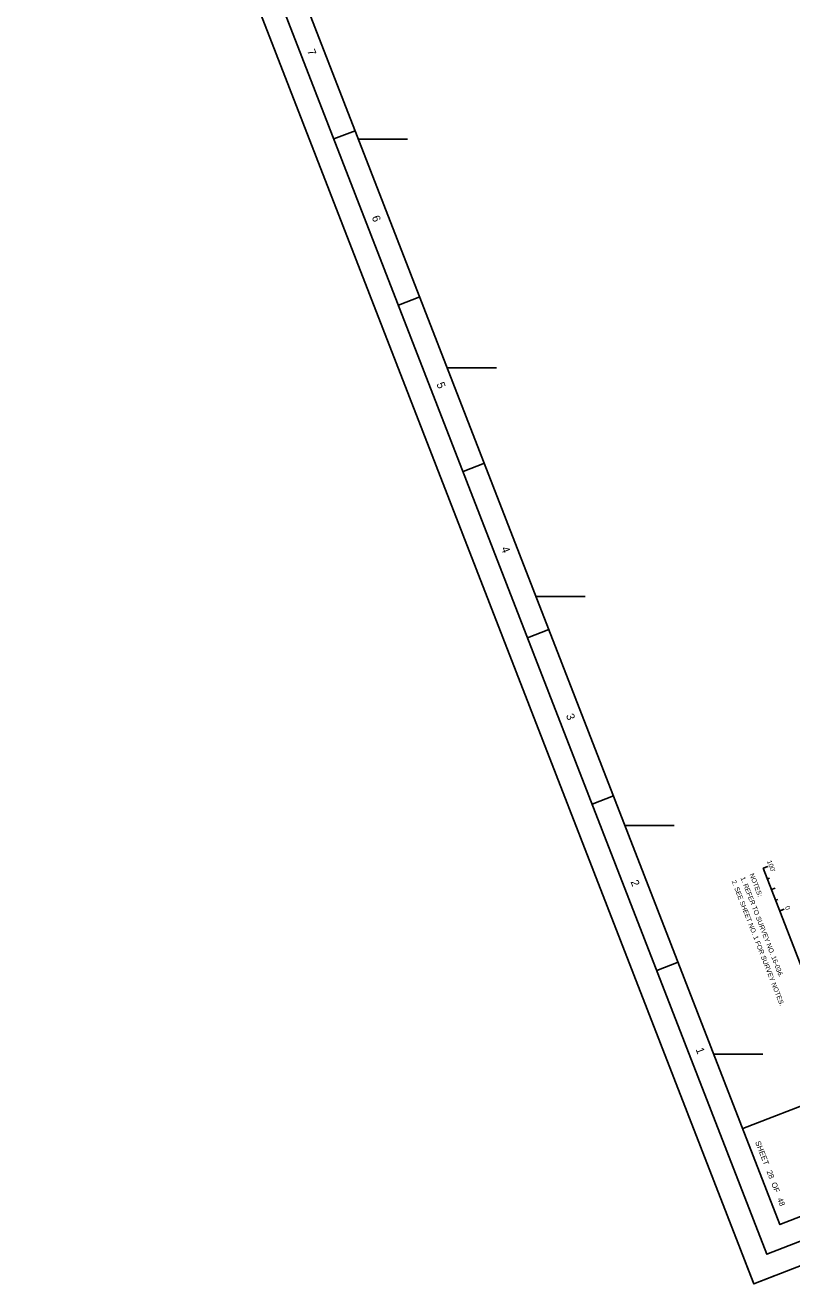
# Model space of a CAD drawing. Extents: x 588973 to 593734, y 821498 to 826830.
# Drawn here: x 588973 to 590647, y 821498 to 824249 of the extents above; entities that cross this region are included whole.
import ezdxf

# ---------------------------------------------------------------- set-up
doc = ezdxf.new("R2010")
doc.units = 0
for name, color, linetype in [('G-ANNO-NPLT', 7, 'Continuous'), ('G-ANNO-TEXT-DRWG', 7, 'Continuous'), ('G-ANNO-TEXT-TTLB', 7, 'Continuous'), ('G-ANNO-TTLB', 7, 'Continuous'), ('V-ANNO-NOTE', 7, 'Continuous'), ('V-TOPO-COOR-STAT', 7, 'Continuous')]:
    doc.layers.add(name, color=color, linetype=linetype)

msp = doc.modelspace()

# ---------------------------------------------------------------- linework, layer by layer
at = {"layer": 'G-ANNO-NPLT'}
msp.add_lwpolyline([(592142.7, 826829.7), (593734.3, 822727.7), (590564.5, 821497.8), (588973, 825599.9)], close=True, dxfattribs=at)
msp.add_lwpolyline([(590611.2, 821515.8), (590564.5, 821497.7), (590546.5, 821544.3)], dxfattribs=at)
at = {"layer": 'G-ANNO-TTLB'}
for p, q in [((589647.2, 824000.5), (589693.8, 824018.6)), ((589788.2, 823636.9), (589834.8, 823655)), ((589929.3, 823273.3), (589975.9, 823291.4)), ((593523.5, 822994.5), (590540.2, 821837)), ((590070.4, 822909.7), (590117, 822927.8)), ((590211.4, 822546.1), (590258, 822564.2)), ((590352.5, 822182.5), (590399.1, 822200.6))]:
    msp.add_line(p, q, dxfattribs=at)
for points in [[(589037.7, 825571.4), (590593, 821562.5), (593669.6, 822756.2), (592114.2, 826765)], [(593604.9, 822784.7), (592112.8, 826630.4), (589129.5, 825472.9), (590621.6, 821627.2)]]:
    msp.add_lwpolyline(points, close=True, dxfattribs=at)
at = {"layer": 'V-ANNO-NOTE'}
for p, q in [((590585, 822406.3), (590594.7, 822410.1)), ((590585, 822406.3), (590693.5, 822126.6)), ((590594, 822383), (590598.5, 822384.7)), ((590603.1, 822359.7), (590611, 822362.8)), ((590612.1, 822336.4), (590616.6, 822338.1)), ((590621.2, 822313.1), (590630.9, 822316.8)), ((590621.2, 822313.1), (590630.9, 822316.8)), ((590621.2, 822313.1), (590625.8, 822314.9))]:
    msp.add_line(p, q, dxfattribs=at)
at = {"layer": 'V-TOPO-COOR-STAT'}
for p, q in [((589701, 824000), (589808.2, 824000)), ((589895, 823500), (590002.2, 823500)), ((590089, 823000), (590196.2, 823000)), ((590282.9, 822500), (590390.2, 822500)), ((590476.9, 822000), (590584.2, 822000))]:
    msp.add_line(p, q, dxfattribs=at)

# ---------------------------------------------------------------- texts
at = {"layer": 'G-ANNO-TEXT-DRWG'}
msp.add_text(' 28          48', height=12, rotation=291.2052, dxfattribs=at).set_placement((590590.4, 821747.6))
at = {"layer": 'G-ANNO-TEXT-TTLB'}
msp.add_text('SHEET         OF', height=12, rotation=291.2052, dxfattribs=at).set_placement((590567.2, 821807.3))
at = {"layer": 'G-ANNO-TTLB'}
for s, p in [('7', (589588.6, 824193)), ('6', (589729.6, 823829.4)), ('5', (589871, 823465)), ('4', (590012.2, 823105.6)), ('3', (590153.9, 822740.3)), ('2', (590294.9, 822376.9)), ('1', (590437.1, 822010.4))]:
    msp.add_text(s, height=17.5, rotation=291.2052, dxfattribs=at).set_placement(p)
at = {"layer": 'V-ANNO-NOTE'}
for s, height, p in [("100'", 10.42, (590592.8, 822421.4)), ('2. SEE SHEET NO. 1 FOR SURVEY NOTES.', 10.416, (590515.8, 822377.6)), ('1. REFER TO SURVEY NO. 16-036.', 10.416, (590535.2, 822385.1)), ('NOTES:', 10.42, (590554.6, 822392.6)), ('0', 10.4, (590632.3, 822321.4))]:
    msp.add_text(s, height=height, rotation=291.2052, dxfattribs=at).set_placement(p)

doc.saveas('drawing.dxf')
